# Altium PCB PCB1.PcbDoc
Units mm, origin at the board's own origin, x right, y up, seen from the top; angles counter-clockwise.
Board outline 65 x 30 mm, 2 copper layers (Top Layer, Bottom Layer), stack 1.201 mm thick; 44 components, 63 nets, 248 pads, 174 vias.
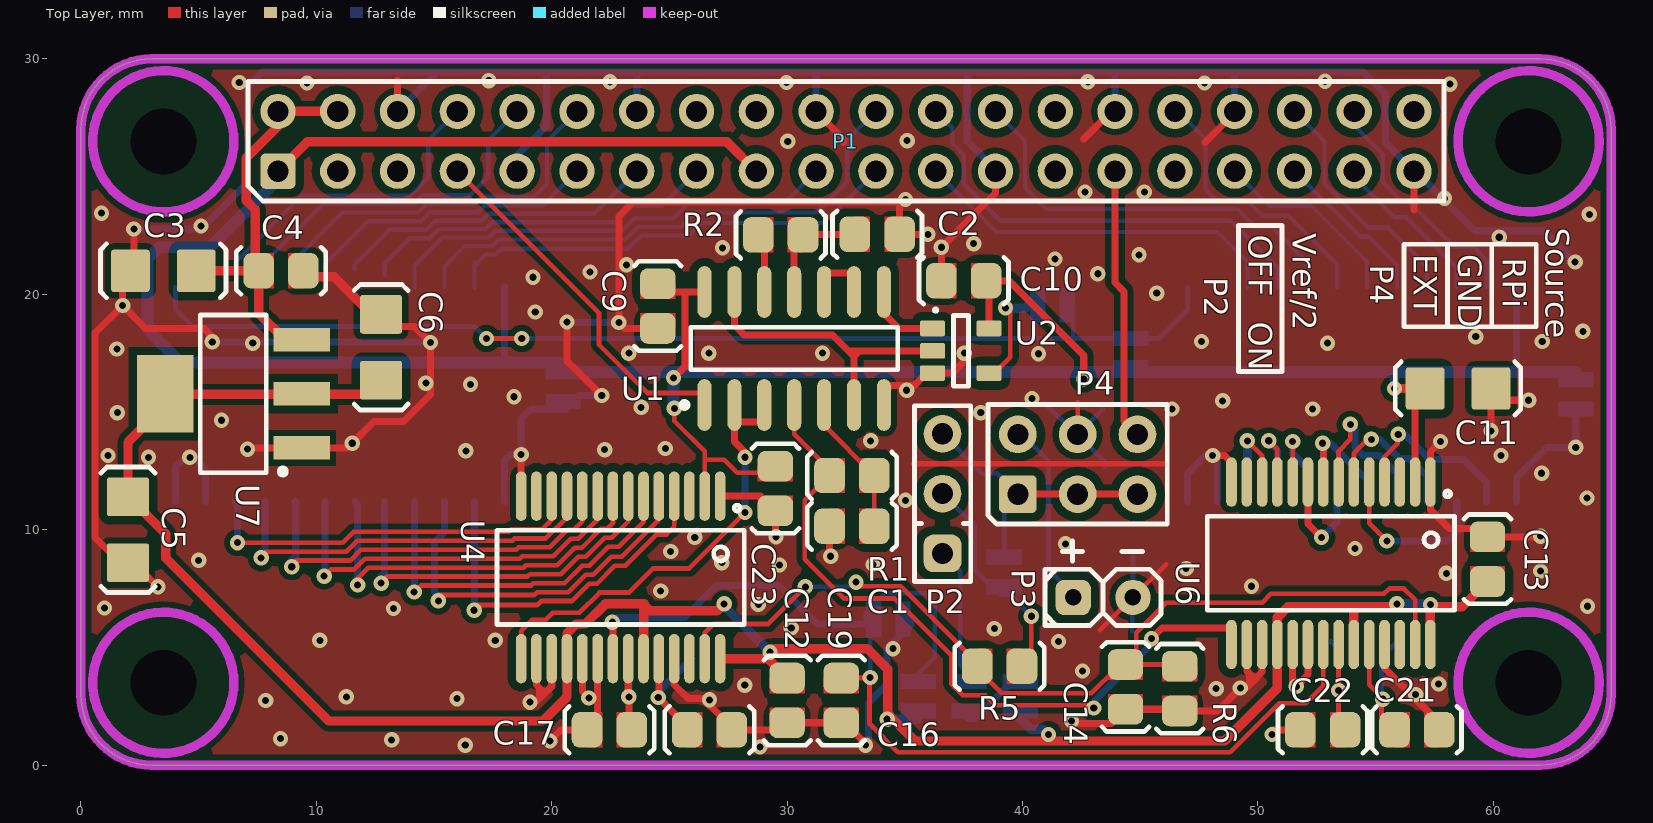
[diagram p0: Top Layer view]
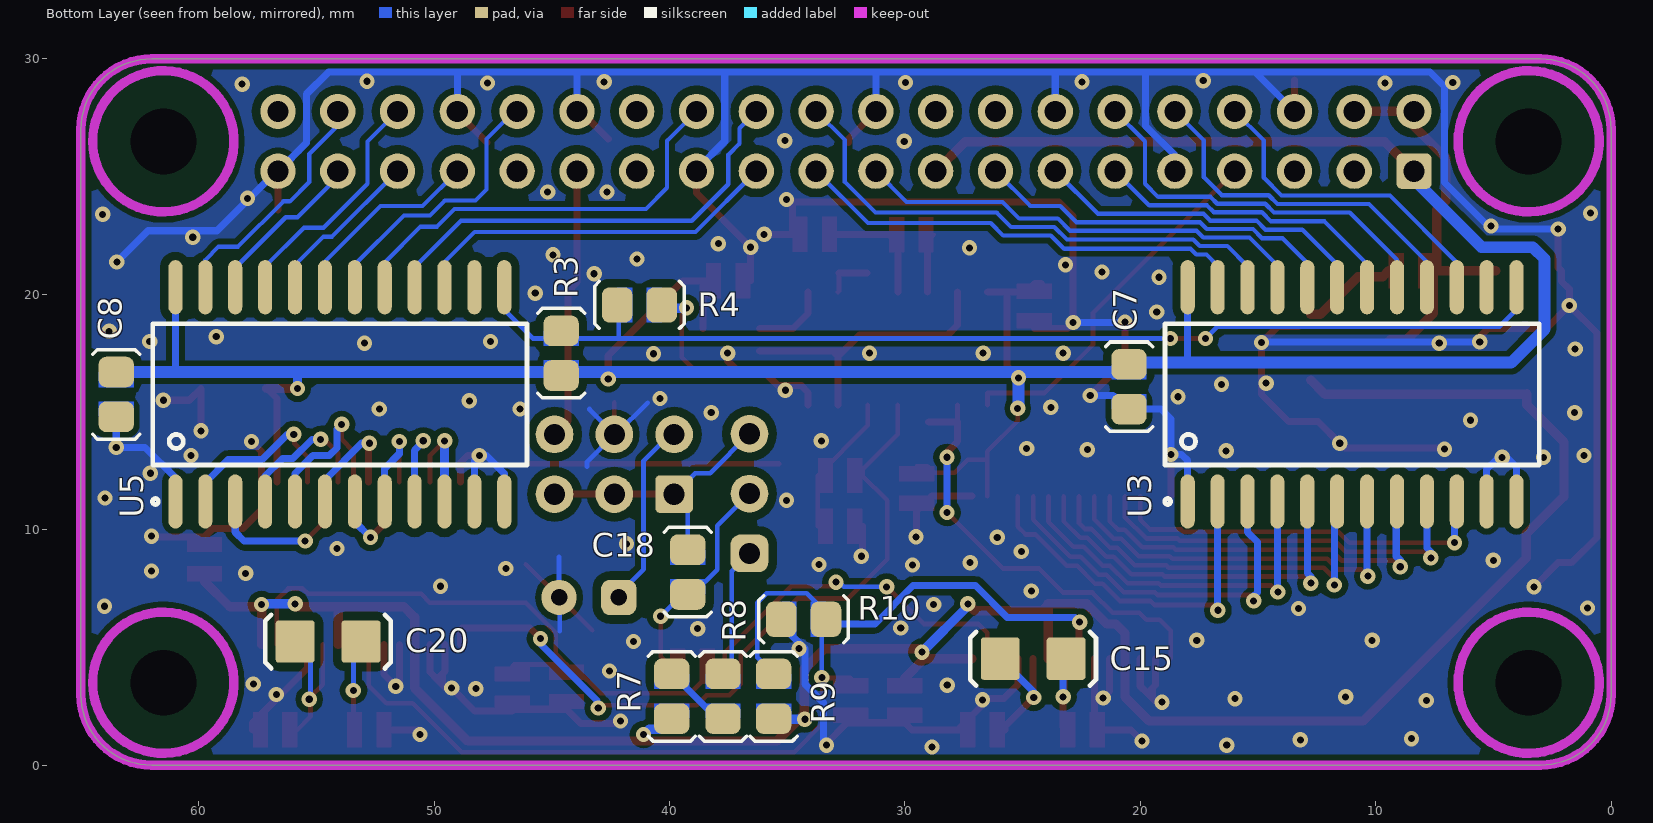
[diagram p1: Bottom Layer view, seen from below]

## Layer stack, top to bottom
Top Solder: solder mask 0.0102, Solder Resist, Dk 3.5
Top Layer: signal copper 0.0356
Dielectric 1: dielectric 1.13, FR-4, Dk 4.8
Bottom Layer: signal copper 0.0356
Bottom Solder: solder mask 0.0102, Solder Resist, Dk 3.5

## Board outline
0,3 0,27 cw(c3,27) 3,30 62,30 cw(c62,27) 65,27 65,3 cw(c62,3) 62,0 3,0 cw(c3,3)

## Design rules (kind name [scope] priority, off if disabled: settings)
Clearance Clearance_2 [Name Like '*-1111'] p1: gap=1 ignorepadtopadclearanceinfootprint=FALSE except(0: Arc-Hole Track-Hole SMDPad-Hole THPad-Hole Via-Hole Fill-Hole Poly-Hole Region-Hole Text-Hole)
Clearance Clearance_1 [InPolygon vs IsPad] p2: gap=0.356 ignorepadtopadclearanceinfootprint=FALSE except(0: Arc-Hole Track-Hole SMDPad-Hole THPad-Hole Via-Hole Fill-Hole Poly-Hole Region-Hole Text-Hole)
Clearance Clearance_3 [InPolygon] p3: gap=0.25 ignorepadtopadclearanceinfootprint=FALSE except(0: Arc-Hole Track-Hole SMDPad-Hole THPad-Hole Via-Hole Fill-Hole Poly-Hole Region-Hole Text-Hole)
Clearance [All] p4: gap=0.18 ignorepadtopadclearanceinfootprint=FALSE except(0: Arc-Hole Track-Hole SMDPad-Hole THPad-Hole Via-Hole Fill-Hole Poly-Hole Region-Hole Text-Hole)
HoleSize [All] p1 off: absolutevalues=TRUE maxlimit=2.54 minlimit=0.025 maxpercent=80.000 minpercent=20.000
PasteMaskExpansion [All] p1: expansion=0.05
PolygonConnect PolygonConnect_1 [All vs IsVia] p1: connectstyle=Direct reliefconductorwidth=0.254 reliefentries=4 polygonreliefangle="90 Angle" airgapwidth=0.254
PolygonConnect [All] p2: connectstyle=NoConnect reliefconductorwidth=0.254 reliefentries=4 polygonreliefangle="90 Angle" airgapwidth=0.254
RoomDefinition Sheet1 [InComponentClass('Sheet1')] p1 off: confinementstyle=ConfineIn formatcopy=TRUE lockcomponents=FALSE outline 411,117.625 393.601,117.625 393.601,70 411,70
RoutingVias [All] p1: holewidth=0.3 width=0.65 viastyle="Through Hole" minholewidth=0.3 minwidth=0.65 maxholewidth=0.3 maxwidth=0.65
SolderMaskExpansion [All] p1: expansion=0.102
Width [All] p1: maxlimit=3.048 minlimit=0.18 preferedwidth=0.18
28 further rules are at their usual default settings.

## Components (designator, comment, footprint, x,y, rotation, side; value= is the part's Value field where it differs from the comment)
C1 "100p" 0805RC 32.75,10.15 r0 top
C2 "N.S." 0805RC 33.825,22.55 r180 top
C3 "10u" 1206RC 3.5,21 r0 top
C4 "0.1u" 0805RC 8.5,21 r180 top
C5 "10u" 1206RC 2,10 r90 top
C6 "10u" 1206RC 12.75,17.75 r270 top
C7 "0.1u" 0805RC 20.475,16.075 r90 bottom
C8 "0.1u" 0805RC 63.5,15.75 r90 bottom
C9 "0.1u" 0805RC 24.5,19.5 r90 top
C10 "0.1u" 0805RC 37.5,20.575 r0 top
C11 "10u" 1206RC 58.5,16 r180 top
C12 "0.1u" 0805RC 30,2.75 r90 top
C13 "0.1u" 0805RC 59.75,8.75 r270 top
C14 "N.S." 0805RC 44.375,3.325 r90 top
C15 "10u" 1206RC 24.55,4.525 r0 bottom
C16 "0.1u" 0805RC 26.7,1.5 r0 top
C17 "0.1u" 0805RC 22.45,1.5 r0 top
C18 "10n" 0805RC 39.225,8.2 r270 bottom
C19 "0.1u" 0805RC 32.3,2.75 r90 top
C20 "10u" 1206RC 54.5,5.25 r0 bottom
C21 "0.1u" 0805RC 56.75,1.5 r0 top
C22 "0.1u" 0805RC 52.75,1.5 r0 top
C23 "0.1u" 0805RC 29.5,11.75 r90 top
P1 "Header 20X2" PLD-40 32.5,26.5 r0 top locked
P2 "PLS-3" PLS-3 36.6,8.995 r270 top
P3 "Header 2" SCSL-2 42.15,7.125 r180 top
P4 "Header 3X2" PBD-6 42.34,12.78 r180 top
R1 "100" 0805R 32.75,12.3 r0 top
R2 "51" 0805R 29.725,22.525 r0 top
R3 "N.S." 0805R 44.6,17.5 r270 bottom
R4 "0" 0805R 41.275,19.55 r0 bottom
R5 "1k" 0805R 39.025,4.2 r0 top
R6 "1k" 0805R 46.675,3.25 r90 top
R7 "1k" 0805R 39.9,2.925 r270 bottom
R8 "1k" 0805R 37.725,2.925 r90 bottom
R9 "150" 0805R 35.575,2.925 r270 bottom
R10 "150" 0805R 34.3,6.2 r180 bottom
U1 "74LVC14AD" M14A_N 30.3,17.7 r90 top
U2 "SN74LVC1G02DBV" SOT-23-5L 37.375,17.6 r0 top
U3 "SN74LVC841ADW" DW024_N 11,15.75 r90 bottom
U4 "AD9200AR" RS-28_N 22.925,7.975 r270 top
U5 "SN74LVC841ADW" DW024_N 54,15.75 r90 bottom
U6 "AD9200AR" RS-28_N 53.1,8.575 r270 top
U7 "LD1117S33TR" SOT223-4N 6.475,15.775 r180 top

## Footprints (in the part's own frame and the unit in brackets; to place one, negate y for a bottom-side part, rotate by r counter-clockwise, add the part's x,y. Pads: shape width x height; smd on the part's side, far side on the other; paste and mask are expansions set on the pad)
0805R [mm] "Chip Resistor"
  rrect50% 1.3x1.5 smd paste-5 mask+0.102: 1(-0.95,0) 2(0.95,0)
  Top Layer region: 0.3,-0.75 0.95,-0.75 0.95,0.75 0.3,0.75
  Top Layer region: -0.95,-0.75 -0.3,-0.75 -0.3,0.75 -0.95,0.75
  silkscreen extent -1.9,-1 1.9,1, body extent -1.15,-0.67 1.15,0.68, height 0.76
0805RC [mm] "Chip Capacitor"
  rrect50% 1.3x1.5 smd paste-5 mask+0.102: 1(-0.95,0) 2(0.95,0)
  Top Layer region: -0.95,-0.75 -0.3,-0.75 -0.3,0.75 -0.95,0.75
  Top Layer region: 0.3,-0.75 0.95,-0.75 0.95,0.75 0.3,0.75
  silkscreen extent -1.9,-1 1.9,1, body extent -0.95,-0.56 1.05,0.64, height 1.2
1206RC [mm] "Chip Capacitor"
  rrect15% 1.65x1.8 smd paste-5: 1(-1.4,0) 2(1.4,0)
  silkscreen extent -2.67,-1.14 2.67,1.14, body extent -1.6,-0.81 1.6,0.79, height 1.6
DW024_N [mm] "SOIC, 24-Leads, Body 15.4x7.5mm, Pitch 1.27mm, IPC Medium Density"
  oval 2.3x0.6 smd: 1(-4.55,6.985) 2(-4.55,5.715) 3(-4.55,4.445) 4(-4.55,3.175) 5(-4.55,1.905) 6(-4.55,0.635) 7(-4.55,-0.635) 8(-4.55,-1.905) 9(-4.55,-3.175) 10(-4.55,-4.445) 11(-4.55,-5.715) 12(-4.55,-6.985) 13(4.55,-6.985) 14(4.55,-5.715) 15(4.55,-4.445) 16(4.55,-3.175) 17(4.55,-1.905) 18(4.55,-0.635) 19(4.55,0.635) 20(4.55,1.905) 21(4.55,3.175) 22(4.55,4.445) 23(4.55,5.715) 24(4.55,6.985)
  silkscreen extent -4.67,-7.95 3,7.96, body extent -5.25,-7.82 5.15,7.58, height 2.6
M14A_N [mm] "SOIC, 14-Leads, Body 8.6x3.9mm, Pitch 1.27mm, IPC Medium Density"
  oval 2.2x0.6 smd paste-5: 1(-2.4,3.81) 2(-2.4,2.54) 3(-2.4,1.27) 4(-2.4,0) 5(-2.4,-1.27) 6(-2.4,-2.54) 7(-2.4,-3.81) 8(2.4,-3.81) 9(2.4,-2.54) 10(2.4,-1.27) 11(2.4,0) 12(2.4,1.27) 13(2.4,2.54) 14(2.4,3.81)
  silkscreen extent -2.52,-4.4 0.9,4.78, body extent -3,-4.37 3,4.38, height 1.75
PBD-6 [mm] "Connector; Header; 5x2 Position"
  rrect25% 1.6x1.6 hole 0.9: 1(2.54,1.27)
  round 1.6 hole 0.9: 2(2.54,-1.27) 3(0,1.27) 4(0,-1.27) 5(-2.54,1.27) 6(-2.54,-1.27)
  silkscreen extent -3.81,-2.54 3.81,2.54, body extent -3.81,-2.5 3.81,2.5, height 8.45
PLD-40 [mm] "Connector 20x2"
  rrect30% 1.5x1.5 hole 0.9: 1(-24.13,-1.27)
  round 1.5 hole 0.9: 2(-24.13,1.27) 3(-21.59,-1.27) 4(-21.59,1.27) 5(-19.05,-1.27) 6(-19.05,1.27) 7(-16.51,-1.27) 8(-16.51,1.27) 9(-13.97,-1.27) 10(-13.97,1.27) 11(-11.43,-1.27) 12(-11.43,1.27) 13(-8.89,-1.27) 14(-8.89,1.27) 15(-6.35,-1.27) 16(-6.35,1.27) 17(-3.81,-1.27) 18(-3.81,1.27) 19(-1.27,-1.27) 20(-1.27,1.27) 21(1.27,-1.27) 22(1.27,1.27) 23(3.81,-1.27) 24(3.81,1.27) 25(6.35,-1.27) 26(6.35,1.27) 27(8.89,-1.27) 28(8.89,1.27) 29(11.43,-1.27) 30(11.43,1.27) 31(13.97,-1.27) 32(13.97,1.27) 33(16.51,-1.27) 34(16.51,1.27) 35(19.05,-1.27) 36(19.05,1.27) 37(21.59,-1.27) 38(21.59,1.27) 39(24.13,-1.27) 40(24.13,1.27)
  silkscreen extent -25.4,-2.54 25.4,2.54, body extent -25.4,-2.54 25.4,2.54, height 8.54
PLS-3 [mm]
  rrect50% 1.6x1.6 hole 0.9: 1(0,0)
  round 1.6 hole 0.9: 2(-2.54,0) 3(-5.08,0)
  silkscreen extent -6.27,-1.19 1.19,1.19, body extent -6.35,-1.27 1.27,1.27, height 8.64
RS-28_N [mm] "SOP, 28-Leads, Body 10.2x5.3mm, Pitch 0.65mm, IPC Medium Density"
  oval 2.1x0.45 smd: 1(-3.45,4.225) 2(-3.45,3.575) 3(-3.45,2.925) 4(-3.45,2.275) 5(-3.45,1.625) 6(-3.45,0.975) 7(-3.45,0.325) 8(-3.45,-0.325) 9(-3.45,-0.975) 10(-3.45,-1.625) 11(-3.45,-2.275) 12(-3.45,-2.925) 13(-3.45,-3.575) 14(-3.45,-4.225) 15(3.45,-4.225) 16(3.45,-3.575) 17(3.45,-2.925) 18(3.45,-2.275) 19(3.45,-1.625) 20(3.45,-0.975) 21(3.45,-0.325) 22(3.45,0.325) 23(3.45,0.975) 24(3.45,1.625) 25(3.45,2.275) 26(3.45,2.925) 27(3.45,3.575) 28(3.45,4.225)
  silkscreen extent -3.07,-5.25 2,5.25, body extent -3.88,-5.16 3.88,5.17, height 2.15
SCSL-2 [mm] "2 pin SCSL connector (DS1002)"
  rrect50% 1.5x1.5 hole 0.7: 1(0,0)
  round 1.5 hole 0.7: 2(-2.54,0)
  silkscreen extent -3.73,-1.19 1.19,1.19, body extent -3.81,-1.27 1.27,1.27, height 4.4
SOT223-4N [mm] "SOT223, 4-Leads, Body 6.5x3.5mm, Pitch 2.3mm, Lead Span 7mm, IPC Medium Density"
  rect 2.4x1 smd: 1(-2.9,2.3) 2(-2.9,0) 3(-2.9,-2.3)
  rect 2.4x3.3 smd: 4(2.9,0)
  silkscreen extent -2.23,-3.35 1.4,3.42, body extent -3.54,-3.25 3.54,3.25, height 1.65
SOT-23-5L [mm] "SOT23, 5-Leads, Body 2.9x1.6mm, Pitch 0.95mm, Lead Span 2.8mm, IPC Medium Density"
  rrect25% 1.067x0.671 smd paste-5: 1(-1.2,0.95) 2(-1.2,0) 3(-1.2,-0.95) 4(1.2,-0.95) 5(1.2,0.95)
  silkscreen extent -1.14,-1.5 0.33,1.8, body extent -1.33,-1.5 1.17,1.5, height 1.1

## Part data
C1 C2 C3 C4 C5 C6 C7 C8 C9 C10 C11 C12 C13 C14 C15 C16 C17 C18 C19 C20 C21 C22 C23: library part Cap, "Capacitor"
P1: "Header, 40-Pin"
P2: library part "Header 3", "3-pin general header"
P3: "2-pin general header"
P4: "Header, 3-Pin, Dual row"
R1 R2 R3 R4 R5 R6 R7 R8 R9 R10: library part Res1, "Resistor"
U1: library part 74ACT14SC, "Hex Schmitt-Trigger Inverter, 14-Pin SOIC, Commercial Grade"
U3 U5: "10-Bit Bus-Interface D-Type Latch with 3-State Outputs"
U4 U6: "Single 10-bit ADC Parallel 20MSPS", Manufacturer="Analog Devices", Part Number=AD9200
U7: "Fixed Low Drop Positive Voltage Regulator, 3.3V, 4-Pin SOT-223, Tape and Reel"

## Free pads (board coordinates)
  round 0 hole 2.8 unplated mask+1.8: 0(3.5,3.5) 0(3.5,26.5) 0(61.5,3.5) 0(61.5,26.5)

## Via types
v1: diameter 0.65, hole 0.3, Top Layer to Bottom Layer, tented both sides, 174 vias

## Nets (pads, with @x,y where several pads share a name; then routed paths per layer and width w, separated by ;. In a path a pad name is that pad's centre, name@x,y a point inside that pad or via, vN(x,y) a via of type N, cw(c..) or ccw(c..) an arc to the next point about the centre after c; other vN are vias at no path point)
+5V: C3.2 C4.2 P1.2 P1.4 U7.3 | length 16.6
  Top Layer w0.4: C3.2 C4.2 7.55,19.2 8.675,18.075 U7.3 ; C4.2@7.406,21.144 7.406,23.594 7.028,23.972 7.028,25.798 8.37,27.14 P1.2 P1.4
A_IN: P1.29 P4.6 | length 11.6
  Top Layer w0.3: P1.29 43.93,20.495 44.3,20.125 44.3,14.63 P4.6
ADC_CLK1: U1.2 U1.3 U4.15 | length 18.9
  Top Layer w0.2: U4.15 18.7,5.7 19.175,6.175 19.75,6.175 20.05,6.475 21.175,6.475 22.03,7.33 23.28,7.33 24.3,8.35 25.827,8.35 v1(28.206,10.729) ; U1.2 U1.2@27.76,14.585 ; v1@28.2,13.3 28.2,13 28.206,13.006 v1(28.206,13.079) ; U1.2@27.76,14.585 27.76,14.575 27.75,14.575 U1.2@27.76,14.585
  Top Layer w0.3: v1@28.2,13.3 27.76,13.74 27.76,14.575 U1.3@29,14.575
  Bottom Layer w0.3: v1(28.206,10.729) v1(28.206,13.079)
ADC_CLK2: R1.1 U1.4 U6.15 | length 31.3
  Top Layer w0.2: U1.4 30.3,14.05 31.8,12.55 R1.1 30.75,11.25 30.75,8.75 32.425,7.075 34.575,7.075 36.975,4.675 36.975,3.45 37.45,2.975 38.425,2.975 38.85,2.55 v1@42.875,2.55
  Top Layer w0.3: v1(45.475,5.375) 45.925,5.825 48.8,5.825 48.875,5.75 U6.15
  Bottom Layer w0.3: v1(43.025,2.425) 43.075,2.475 43.075,2.75 45.475,5.15 v1(45.475,5.375) v1@45.4,5.3
AVCC: C5.2 C6.2 C12.2 C13.2 R7.2 R9.2 U4.18 U4.23 U4.28 U6.18 U6.23 U6.28 U7.2 U7.4 | length 100.8
  Top Layer w0.4: C6.2 12.15,15.75 3.6,15.75 U7.4 3.575,15.3 2,13.725 C5.2 2.025,11.4 3.6,9.825 3.6,8.8 10.525,1.875 19.625,1.875 20.65,2.9 U4.18 20.65,5.6 21.045,5.995 21.424,5.995 22.279,6.85 23.925,6.85 ; U4.23 23.9,6.825 24.175,6.55 27.025,6.55 v1(27.325,6.85) ; U4.28 29.175,4.525 C12.2 ; v1(29.275,4.8) 29.425,4.95 33.4,4.95 34.265,4.085 v1@34.265,1.965 ; v1(34.25,1.95) v1@34.265,1.965 ; v1@34.35,2.05 v1@34.265,1.965 ; v1@34.375,2.075 35.425,1.025 48.575,1.025 50.825,3.275 U6.18 50.825,6.275 51.275,6.725 54.075,6.725 ; U6.23 54.075,6.725 ; v1(55.9,6.85) 55.9,6.725 54.075,6.725 ; U6.28 57.325,6.725 58.675,6.725 C13.2
  Bottom Layer w0.4: v1(27.325,6.85) 27.325,6.75 v1(29.275,4.8) v1@29.35,4.8 ; v1(34.25,1.95) R9.2@35.525,1.95 ; R7.2 40.35,1.525 40.85,1.525 41.075,1.3 v1(41.1,1.3) ; v1(55.9,6.85) 57.3,6.85 v1(57.325,6.825)
CLK_IN: P1.7 U1.1 | length 15.7
  Top Layer w0.2: P1.7 22.006,19.214 22.006,17.869 24.07,15.805 26.49,15.805 U1.1
DA0: P1.21 U3.23 | length 19.8
  Bottom Layer w0.18: U3.23 U3.23@16.715,21.215 ; U3.23@16.715,21.34 U3.23@16.715,21.215 ; P1.21 31.565,23.025 26.35,23.025 25.825,22.5 23.8,22.5 23.233,21.933 17.867,21.933 17.624,21.69 17.19,21.69 U3.23@16.715,21.215
DA1: P1.22 U3.22 | length 23
  Bottom Layer w0.18: U3.22 15.445,21.195 16.3,22.05 17.475,22.05 17.75,22.325 23.116,22.325 23.651,22.86 25.485,22.86 26.1,23.475 31.25,23.475 32.55,24.775 32.55,26.55 P1.22
DA2: P1.19 U3.21 | length 19.6
  Bottom Layer w0.18: U3.21 14.175,21.222 15.363,22.41 17.326,22.41 17.616,22.7 22.982,22.7 23.502,23.22 25.145,23.22 25.85,23.925 29.925,23.925 P1.19
DA3: P1.15 U3.20 | length 15.4
  Bottom Layer w0.18: U3.20@12.905,20.8 12.905,21.33 13.955,22.38 14.824,22.38 15.214,22.77 17.177,22.77 17.467,23.06 22.71,23.06 23.4,23.75 24.67,23.75 P1.15
DA4: P1.13 U3.19 | length 13.8
  Bottom Layer w0.18: U3.19@11.635,21.05 11.635,21.26 13.115,22.74 14.675,22.74 15.065,23.13 17.028,23.13 17.318,23.42 21.8,23.42 P1.13
DA5: P1.11 U3.18 | length 12.6
  Bottom Layer w0.18: U3.18@10.365,21.05 10.365,21.29 12.175,23.1 14.45,23.1 14.84,23.49 16.879,23.49 17.169,23.78 19.62,23.78 P1.11
DA6: P1.12 U3.17 | length 16.1
  Bottom Layer w0.18: U3.17@9.095,21.05 9.095,21.47 11.1,23.475 14.316,23.475 14.691,23.85 16.729,23.85 17.019,24.14 19.24,24.14 19.8,24.7 19.8,26.5 P1.12
DA7: P1.10 U3.16 | length 14.6
  Bottom Layer w0.18: U3.16@7.825,21.05 7.825,21.375 10.285,23.835 14.167,23.835 14.542,24.21 16.535,24.21 17.3,24.975 17.3,26.54 P1.10
DA8: P1.8 U3.15 | length 13.3
  Bottom Layer w0.18: U3.15@6.555,21.05 6.555,21.355 9.395,24.195 13.995,24.195 14.75,24.95 14.75,26.53 P1.8
DB0: P1.38 U5.23 | length 10.4
  Bottom Layer w0.18: P1.38 54.09,27.166 55.3,25.956 55.3,24.775 56.125,23.95 56.4,23.95 58.325,22.025 59.15,22.025 59.715,21.46 U5.23
DB1: P1.37 U5.22 | length 7
  Bottom Layer w0.18: P1.37 54.09,24.985 55.8,23.275 56.3,23.275 58.445,21.13 U5.22
DB2: P1.36 U5.21 | length 10.3
  Bottom Layer w0.18: P1.36 52.825,26.495 52.825,24.7 54.7,22.825 55.525,22.825 57.175,21.175 U5.21
DB3: P1.35 U5.20 | length 7
  Bottom Layer w0.18: P1.35 54.33,22.45 54.7,22.45 55.905,21.245 U5.20
DB4: P1.33 U5.19 | length 8.3
  Bottom Layer w0.18: P1.33 50.49,23.75 52.275,23.75 54.635,21.39 U5.19
DB5: P1.32 U5.18 | length 11.8
  Bottom Layer w0.18: P1.32 46.605,27.77 47.775,26.6 47.775,24.45 48.24,23.985 49.54,23.985 50.175,23.35 51.275,23.35 53.365,21.26 U5.18
DB6: P1.26 U5.17 | length 18.1
  Bottom Layer w0.18: P1.26 40.1,26.52 40.1,24.525 41,23.625 49.125,23.625 49.875,22.875 50.575,22.875 52.095,21.355 U5.17
DB7: P1.24 U5.16 | length 19.2
  Bottom Layer w0.18: P1.24 37.025,27.055 37.025,26.4 37.5,25.925 37.5,24.675 39.05,23.125 48.85,23.125 50.825,21.15 U5.16
DB8: P1.23 U5.15 | length 15.9
  Bottom Layer w0.18: P1.23 38.89,22.65 48.275,22.65 49.555,21.37 U5.15
GND: C1.1 C2.1 C3.1 C4.1 C5.1 C6.1 C7.1 C8.1 C9.1 C10.1 C11.1 C12.1 C13.1 C14.1 C16.2 C17.1 C19.1 C21.2 C22.1 C23.1 P1.6 P1.9 P1.14 P1.20 P1.25 P1.30 P1.34 P1.39 P3.2 P4.4 R6.1 R10.1 U1.7 U2.3 U3.1 U3.11 U3.12 U4.1 U4.14 U4.16 U4.17 U4.19 U4.20 U4.25 U5.1 U5.11 U5.12 U6.1 U6.14 U6.16 U6.17 U6.19 U6.20 U6.25 U7.1 | length 300.1
  Top Layer w0.2: P4.4 42.34,15.415 ; 43.275,5.725 P3.2@44.675,7.125 ; P3.2@44.65,7.3 P3.2@44.665,7.3 ; P3.2 46.1,8.535
  Top Layer w0.22: 35.35,12.8 46,12.8
  Top Layer w0.3: v1(2.25,22.775) 2.25,21.15 C3.1 2.1,20.55 1.775,20.225 v1(1.775,19.525) ; v1(3.275,7.575) 2.25,8.6 C5.1 1.675,8.6 0.6,9.675 0.6,18.35 v1(1.775,19.525) ; v1(5.58,17.979) 5.559,18 5.559,18.216 5.225,18.55 2.75,18.55 v1(1.775,19.525) ; v1@7.125,13.475 U7.1 11.325,13.475 v1(11.525,13.675) 12.45,14.6 13.7,14.6 14.85,15.75 v1(14.85,17.95) 14.175,18.625 C6.1@13.275,18.625 ; P1.6 13.45,29.1 ; U4.14 v1(18.7,13.2) ; v1(19.075,2.675) 19.325,2.675 19.475,2.825 ; U4.16 19.35,3.4 19.475,3.275 ; v1(19.925,1.025) 20.4,1.5 C17.1 ; U4.17 20,3.35 19.7,3.05 ; v1(20.65,18.825) 20.65,17.175 v1(22.125,15.7) ; U4.19 21.3,3.125 v1(21.575,2.85) 21.95,2.85 ; C17.1@21.95,1.95 21.95,2.85 ; U4.20 21.95,2.85 ; C9.1 23.1,18.55 v1(22.85,18.8) 22.85,23.325 23.45,23.925 34.775,23.925 C2.1 v1(35.975,22.55) ; U4.25 25.2,3.425 25.8,2.825 26.425,2.825 C16.2@27.65,1.6 ; U4.1 28.875,11.425 C23.1 29.5,9.725 v1(29.525,9.7) ; C16.2 29.7,1.5 C12.1 C19.1 32.45,1.8 33.325,0.925 v1(33.325,0.85) ; P1.20 32.4,26.6 32.4,26.45 ; C1.1 31.8,8.925 v1(31.85,8.875) ; U1.7 34.11,15.835 34.4,16.125 35.4,16.125 35.925,16.65 U2.3 37,16.65 37.525,17.175 v1(37.525,17.5) ; C10.1 v1(36.55,22) 38.85,24.3 P1.25 ; v1(42.075,1.875) 42.18,1.77 43.77,1.77 C14.1 46.6,2.375 R6.1 48.275,2.3 v1(49.25,3.275) 49.5,3.275 49.65,3.425 ; 42.6,26.6 43.77,27.77 P1.30 ; 47.75,26.45 49.01,27.71 P1.34 ; v1(48.075,13.15) 48.575,13.15 48.875,12.85 U6.14 ; U6.16 49.525,4 49.65,3.875 ; U6.17 50.175,3.95 49.875,3.65 ; v1(50.6,1.3) 50.6,1.5 C22.1 ; U6.19 51.475,3.5 v1(51.625,3.35) 52.125,3.85 U6.20 ; U6.25 55.375,4.125 57.7,1.8 C21.2 ; 56.63,23.58 P1.39 ; v1(57.75,13.75) 57.325,13.325 U6.1 57.325,10.85 58.125,10.05 59.4,10.05 C13.1 61.975,9.7 v1(62,9.725) ; v1@59.9,14.45 C11.1 60.4,15.5 v1(61.5,15.5) ; 19.475,2.825 19.7,3.05 ; 19.475,2.825 19.475,3.275 ; 19.475,3.275 19.7,3.05 ; 49.65,3.425 49.65,3.875 ; 49.65,3.425 49.875,3.65 ; 49.65,3.875 49.875,3.65
  Top Layer w0.4: C4.1 9.7,20.75 10.75,20.75 12.35,19.15 C6.1
  Bottom Layer w0.2: 40.925,15.4 42.275,14.05 P4.4 ; 43.4,15.125 43.4,15.11 P4.4 ; 43.5,12.675 43.5,12.89 P4.4 ; 44.665,5.685 P3.2@44.665,7.3 ; P3.2 44.69,8.84
  Bottom Layer w0.3: v1(2.25,22.775) 5.1,22.775 7.075,24.75 7.075,28.825 7.7,29.45 15.13,29.45 ; U3.12 4.015,12.665 4.375,13.025 4.825,13.025 5.285,12.565 U3.11 ; v1(5.58,17.979) 14.821,17.979 v1(14.85,17.95) ; P1.6 15.13,29.45 ; U3.1 17.985,12.935 18.25,13.2 v1(18.7,13.2) 18.7,14.7 19.125,15.125 C7.1 20.575,15.125 21.15,15.7 v1(22.125,15.7) v1@22,15.575 ; P1.9 18.53,25.905 19.775,27.15 19.775,29.375 ; v1(20.65,18.825) 20.675,18.8 v1(22.85,18.8) ; P1.14 23.61,29.44 23.6,29.45 ; P1.20 31.23,29.445 31.225,29.45 ; v1@33.45,0.925 33.45,2.65 34.25,3.45 34.25,4.95 35.25,5.95 R10.1 ; P1.25 38.85,25.3 37.65,26.5 37.65,29.45 ; P1.30 43.93,29.38 ; U5.12 47.015,12.39 47.775,13.15 v1(48.075,13.15) 48.285,12.94 U5.11 ; P1.34 49.01,29.41 ; U5.1 60.985,12.21 62.275,13.5 v1(63.5,13.5) C8.1 ; v1(63.475,21.375) 62.15,22.7 59.225,22.7 56.695,25.23 P1.39 56.62,25.23 55.425,26.425 55.425,28.5 54.475,29.45 37.65,29.45 ; 15.13,29.45 23.6,29.45 ; 23.6,29.45 31.225,29.45 ; 31.225,29.45 37.65,29.45
  other v1: 28.85,0.775 16.325,0.85 13.2,1.075 8.475,1.125 7.85,2.75 26.7,2.775 15.975,2.825 11.275,2.9 56.7,3 48.225,3.25 28.2,3.4 57.675,3.45 42.55,4 34.5,4.95 41.525,5.25 10.15,5.3 17.6,5.3 38.8,5.8 30.175,5.825 13.275,6.65 1,6.675 64,6.75 28.775,6.825 24.625,7.4 49.725,7.6 58,8.15 62,8.25 46.95,8.35 29.675,8.5 33.65,8.525 27.225,8.6 5,8.7 25.05,9.075 54.125,9.2 41.825,9.4 26.075,9.675 35.025,11.25 63.975,11.35 62.05,12.4 2.875,13.075 4.625,13.075 1.15,13.15 60.325,13.15 16.35,13.35 22.25,13.4 7.075,13.425 24.825,13.45 33.55,13.775 59.9,14.2 5.975,14.65 1.55,14.975 38.225,14.975 46.35,15.125 52.325,15.125 23.8,15.2 48.5,15.475 40.4,15.575 18.4,15.65 35.075,15.925 16.55,16.175 14.65,16.225 40.675,17.475 23.275,17.5 26.675,17.5 31.5,17.5 1.525,17.675 7.3,17.925 52.95,17.925 47.6,18 62.075,18 59.25,18.2 63.8,18.425 19.3,19.25 45.7,20.05 19.2,20.725 43.2,20.875 21.625,20.95 23.175,21.25 41.375,21.5 44.95,21.675 27.25,21.975 37.925,22.15 60.25,22.425 5.1,22.9 64.075,23.4 0.875,23.45 35.025,24.025 57.925,24.075 42.65,24.35 45.175,24.35 30.025,26.5 35.1,26.525 58.15,28.925 9.6,28.975 47.725,28.975 6.725,29 29.975,29 22.475,29.025 42.775,29.025 52.85,29.05 17.325,29.075
LATCH: R3.1 R4.2 U3.13 U5.13 | length 47.4
  Top Layer w0.2: v1(17.225,18.125) v1(18.725,18.125)
  Bottom Layer w0.2: U3.13 4.015,19.36 4.737,18.638 16.712,18.638 v1(17.225,18.125) ; v1(18.725,18.125) 42.175,18.125 ; R4.2@42.15,19.55 42.15,18.15 42.175,18.125 ; U5.13 47.015,19.34 45.8,18.125 42.175,18.125
NetC1_2: C1.2 R1.2 U1.5 | length 6
  Top Layer w0.2: U1.5 31.57,14.43 R1.2 C1.2
NetC2_2: C2.2 R2.2 U1.11 | length 4.8
  Top Layer w0.2: R2.2@30.3,22.15 R2.2
  Top Layer w0.3: U1.11 R2.2@30.3,22.15 ; R2.2 30.7,22.55 C2.2
NetC14_2: C14.2 R5.1 R6.2 U4.27 U6.27 | length 41.1
  Top Layer w0.2: U4.27 26.5,5.625 26.875,6 29.2,6 v1(30.775,7.575) ; v1@32.875,7.775 v1(32.925,7.775) 33.1,7.6 34.825,7.6 37.65,4.775 37.65,4.525 39.125,3.05 42.925,3.05 44,4.125 44.225,4.125 C14.2 ; R6.2 46.6,4.275 C14.2 ; U6.27 56.675,7.025 56.2,7.5 55.575,7.5 55.35,7.275 50.55,7.275 50.175,6.9 46.095,6.9 44.825,5.63 44.825,4.725 C14.2
  Bottom Layer w0.2: v1(30.775,7.575) 32.6,7.575 32.8,7.775 v1(32.925,7.775)
NetC15_1: C15.1 C17.2 U4.22 | length 4.6
  Top Layer w0.3: U4.22 23.25,2.925 v1(23.275,2.9) C17.2@23.275,1.625
  Bottom Layer w0.3: C15.1 23.275,4.4 v1(23.275,2.9)
NetC15_2: C15.2 C16.1 U4.24 | length 5.8
  Top Layer w0.3: U4.24 24.55,2.9 v1(24.525,2.875) 25.75,1.65 C16.1
  Bottom Layer w0.3: v1(24.525,2.875) 24.525,3.1 C15.2
NetC18_1: C18.1 P2.3 P4.1 P4.3 P4.5 | length 11.9
  Top Layer w0.3: P4.1 P4.3 P4.5
  Bottom Layer w0.2: P2.3 38.275,12.4 38.91,12.4 P4.1 39.225,10.935 C18.1
NetC18_2: C18.2 P2.2 R5.2 | length 9.3
  Top Layer w0.2: R5.2 40.375,4.6 v1(40.375,6.325)
  Bottom Layer w0.2: P2.2 37.975,10.16 37.975,8.3 39.025,7.25 C18.2 39.45,7.25 v1(40.375,6.325)
NetC20_1: C20.1 C22.2 U6.22 | length 5.6
  Top Layer w0.2: C22.2@53.425,1.775 v1(53.425,3.175) U6.22
  Bottom Layer w0.2: C20.1 53.425,4.925 v1(53.425,3.175)
NetC20_2: C20.2 C21.1 U6.24 | length 6.8
  Top Layer w0.2: U6.24 54.725,3.425 55.25,2.9 55.25,2.05 C21.1
  Bottom Layer w0.2: v1(55.3,2.8) 55.25,2.85 55.25,4.6 C20.2
NetP2_1: P2.1 R8.2 | length 5.6
  Bottom Layer w0.2: P2.1 37.35,8.245 37.35,4.25 R8.2
NetP3_1: P3.1 P4.2 | length 7.8
  Bottom Layer w0.2: P4.2 39.975,14.05 41.1,12.925 41.1,8.325 P3.1@42.125,7.3
NetR2_1: R2.1 U1.12 | length 2.5
  Top Layer w0.2: R2.1 R2.1@29.03,22.27
  Top Layer w0.3: U1.12 R2.1@29.03,22.27
NetR4_1: R4.1 U2.4 | length 4.4
  Top Layer w0.2: U2.4 38.8,16.65 39.475,17.325 39.475,19.224 v1(39.274,19.425)
  Bottom Layer w0.4: v1(39.274,19.425) 39.299,19.4 40.1,19.4 R4.1@40.25,19.55
NetR7_1: R7.1 R8.1 | length 2.9
  Bottom Layer w0.3: R8.1@37.675,1.975 R8.1 R8.1@37.925,1.975 ; R8.1@37.975,1.975 R7.1@39.875,3.875
NetU1_6: U1.6 U1.13 U2.2 | length 13
  Top Layer w0.3: U1.13 27.76,18.69 28.175,18.275 31.925,18.275 32.6,17.6 ; U1.6 32.84,17.36 ; U2.2 33.08,17.6 ; 32.6,17.6 32.84,17.36 ; 32.6,17.6 33.08,17.6 ; 32.84,17.36 33.08,17.6
NetU1_8: U1.8 U2.1 | length 3.2
  Top Layer w0.3: U1.8 34.11,19.19 34.75,18.55 U2.1
NetU1_9: U1.9 U1.10 | length 2
  Top Layer w0.2: U1.9@32.8,20.9 32.8,20.14 U1.9
  Top Layer w0.3: U1.10@31.6,20.9 U1.9@32.8,20.9
NetU3_2: U3.2 U4.4 | length 16
  Top Layer w0.2: v1@16.65,6.634 16.816,6.8 19.38,6.8 19.55,6.97 20.857,6.97 21.597,7.71 21.922,7.71 22.682,8.47 23.132,8.47 24.462,9.8 24.875,9.8 25.2,10.125 U4.4
  Top Layer w0.3: v1@16.65,6.634 v1(16.706,6.579)
  Bottom Layer w0.3: v1(16.706,6.579) 16.715,6.588 U3.2
NetU3_3: U3.3 U4.5 | length 16.4
  Top Layer w0.2: v1(15.181,6.979) 15.2,6.998 15.2,7.225 19.25,7.225 19.375,7.35 20.7,7.35 21.44,8.09 21.765,8.09 22.525,8.85 22.975,8.85 24.55,10.425 U4.5
  Bottom Layer w0.3: v1(15.181,6.979) 15.181,7.181 15.025,7.336 15.025,9.475 15.445,9.895 U3.3
NetU3_4: U3.4 U4.6 | length 15.9
  Top Layer w0.2: v1(14.156,7.354) 14.432,7.63 19.118,7.63 19.218,7.73 20.543,7.73 21.288,8.475 21.6,8.475 22.4,9.275 22.837,9.275 23.9,10.338 U4.6
  Bottom Layer w0.3: v1(14.156,7.354) 14.175,7.373 U3.4
NetU3_5: U3.5 U4.7 | length 16.2
  Top Layer w0.2: v1(12.756,7.729) 12.756,7.781 12.985,8.01 18.96,8.01 19.06,8.11 20.385,8.11 21.13,8.855 21.443,8.855 22.243,9.655 22.555,9.655 23.25,10.35 U4.7
  Bottom Layer w0.2: v1@12.756,7.706 v1(12.756,7.729)
  Bottom Layer w0.3: v1(12.756,7.729) 12.756,8.006 12.905,8.155 U3.5
NetU3_6: U3.6 U4.8 | length 16.8
  Top Layer w0.2: v1(11.755,7.654) 11.75,7.659 11.75,7.93 12.21,8.39 18.803,8.39 18.903,8.49 20.228,8.49 20.973,9.235 21.285,9.235 22.085,10.035 22.36,10.035 22.6,10.275 U4.8
  Bottom Layer w0.2: v1(11.755,7.654) v1@11.755,7.795
  Bottom Layer w0.3: U3.6 11.755,11.08 v1@11.755,7.795
NetU3_7: U3.7 U4.9 | length 16.8
  Top Layer w0.2: v1(10.33,8.029) 10.612,8.31 11.593,8.31 12.053,8.77 18.645,8.77 18.745,8.87 20.07,8.87 20.815,9.615 21.128,9.615 21.95,10.437 U4.9
  Bottom Layer w0.3: v1(10.33,8.029) 10.365,8.063 U3.7
NetU3_8: U3.8 U4.10 | length 17.1
  Top Layer w0.2: v1(8.955,8.429) 8.955,8.505 9.14,8.69 11.435,8.69 11.895,9.15 18.488,9.15 18.588,9.25 19.913,9.25 20.658,9.995 20.945,9.995 21.3,10.35 U4.10
  Bottom Layer w0.3: v1(8.955,8.429) 8.955,8.705 9.125,8.875 9.125,11.17 U3.8
NetU3_9: U3.9 U4.11 | length 17.1
  Top Layer w0.2: v1(7.655,8.804) 7.655,8.88 7.845,9.07 11.278,9.07 11.738,9.53 18.331,9.53 18.431,9.63 19.744,9.63 20.65,10.536 U4.11
  Bottom Layer w0.3: v1(7.655,8.804) 7.655,9.055 7.825,9.225 U3.9
NetU3_10: U3.10 U4.12 | length 16.5
  Top Layer w0.2: v1(6.65,9.45) 11.12,9.45 11.58,9.91 18.173,9.91 18.273,10.01 19.585,10.01 20,10.425 U4.12
  Bottom Layer w0.3: U3.10 6.65,11.105 v1(6.65,9.45)
NetU5_2: U5.2 U6.4 | length 7.7
  Top Layer w0.2: U6.4 55.375,13.1 55.925,13.65 55.925,14.021 v1(55.958,14.054)
  Bottom Layer w0.3: v1(55.958,14.054) 56.221,14.054 57.3,12.975 58.75,12.975 59.715,12.01 U5.2
NetU5_3: U5.3 U6.5 | length 7.2
  Top Layer w0.2: U6.5 54.725,10.275 v1(55.475,9.525)
  Bottom Layer w0.3: v1(55.475,9.525) 58.075,9.525 58.445,9.895 U5.3
NetU5_4: U5.4 U6.6 | length 6.3
  Top Layer w0.2: U6.6 54.075,13.25 54.665,13.84 v1(54.815,13.84)
  Bottom Layer w0.3: v1(54.815,13.84) 55.185,13.84 56,13.025 56.425,13.025 57.175,12.275 U5.4
NetU5_5: U5.5 U6.7 | length 7.2
  Top Layer w0.2: U6.7 53.425,13.337 53.925,13.837 v1(53.925,14.475)
  Bottom Layer w0.3: v1(53.925,14.475) 54.125,14.275 54.125,13.475 54.45,13.15 55.15,13.15 55.905,12.395 U5.5
NetU5_6: U5.6 U6.8 | length 5.1
  Top Layer w0.3: v1(52.75,13.675) 52.775,13.65 U6.8
  Bottom Layer w0.3: v1(52.75,13.675) 53.075,13.675 54.635,12.115 U5.6
NetU5_7: U5.7 U6.9 | length 4.4
  Top Layer w0.3: U6.9 52.125,10.25 v1(52.7,9.675)
  Bottom Layer w0.3: v1(52.7,9.675) 53.365,10.34 U5.7
NetU5_8: U5.8 U6.10 | length 4.5
  Top Layer w0.2: U6.10 v1(51.475,13.75)
  Bottom Layer w0.3: v1(51.475,13.75) 51.475,13.225 52.095,12.605 U5.8
NetU5_9: U5.9 U6.11 | length 4.7
  Top Layer w0.2: v1@50.425,13.811 v1(50.457,13.779) 50.825,13.411 U6.11
  Bottom Layer w0.3: v1(50.457,13.779) 50.45,13.772 50.45,13.75 50.825,13.375 U5.9
NetU5_10: U5.10 U6.12 | length 4.6
  Top Layer w0.2: v1(49.55,13.775) 50.175,13.15 U6.12
  Bottom Layer w0.4: v1(49.55,13.775) 49.555,13.77 U5.10
REF_T: C19.2 R9.1 R10.2 U4.21 U6.21 | length 49.6
  Top Layer w0.2: C19.2@32.85,3.15 C19.2 v1@33.5,3.7 ; v1(33.525,3.725) v1@33.5,3.7 ; U6.21 52.775,3.375 52.025,2.625 50.9,2.625 48.82,0.545 34.705,0.545 33.5,1.75 v1@33.5,3.7
  Top Layer w0.3: v1(22.575,6.075) 22.6,6.05 U4.21
  Bottom Layer w0.2: R10.2 33.35,6.475 34.175,7.3 35.875,7.3 36.275,6.9 36.275,4.575 R9.1 ; v1(33.525,3.725) R10.2@33.525,6.025
  Bottom Layer w0.3: v1(22.575,6.075) 22.775,6.275 25.65,6.275 27,7.625 29.65,7.625 31.275,6 R10.2@33.325,6
VCC: C7.2 C8.2 C9.2 C10.2 C11.2 C23.2 P1.1 P1.17 R3.2 U1.14 U2.5 U3.24 U4.2 U5.24 U6.2 | length 130.4
  Top Layer w0.2: v1(25.206,15.154) 25.206,14.619 26.5,13.325 26.5,12.975 ; U4.2 26.5,12.975 ; C23.2 29.025,12.7 28.75,12.425 27.875,12.425 27.325,12.975 26.5,12.975
  Top Layer w0.3: C9.2@24.2,20.45 C9.2 24.85,20.1 25.67,20.1 ; v1(25.175,16.45) 25.67,16.945 25.67,20.1 ; U1.14 25.67,20.1 ; U2.5 38.575,20.45 C10.2 39.425,20.575 42.6,17.4 v1(42.6,16.4) ; U6.2 56.675,15.575 C11.2
  Top Layer w0.4: P1.1 9.615,26.475 27.445,26.475 P1.17 ; v1(55.8,16) C11.2
  Bottom Layer w0.3: 17.985,17.05 17.985,17.1 U3.24 ; v1(42.6,16.4) 42.6,16.65 v1@42.65,16.7 ; U5.24 60.985,16.815 61.1,16.7
  Bottom Layer w0.4: v1(55.8,16) 55.8,16.7
  Bottom Layer w0.5: P1.1 8.37,24.87 5.5,22 3.325,22 2.825,21.5 2.825,18.525 4.25,17.1 17.985,17.1 C7.2@20.325,17.1 ; C7.2@20.125,17.075 20.5,16.7 42.65,16.7 55.8,16.7 61.1,16.7 C8.2 ; v1(25.175,16.45) 25.175,15.185 v1(25.206,15.154)
pads on no net: P1.3 P1.5 P1.16 P1.18 P1.27 P1.28 P1.31 P1.40 U3.14 U4.3 U4.13 U4.26 U5.14 U6.3 U6.13 U6.26

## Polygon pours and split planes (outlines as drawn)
GND on Bottom Layer "B1p" (solid, remove dead copper, pour order 2): 0,30 0,0 65,0 65,30
GND on Top Layer "B1p" (solid, remove dead copper, pour order 4): 0,0 0,30 65,30 65,0

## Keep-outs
Keep-Out Layer:
  circle w0.4: c3.5,26.5 r3
  circle w0.4: c3.5,3.5 r3
  circle w0.4: c61.5,3.5 r3
  circle w0.4: c61.5,26.5 r3
  lines w0.4: 0,3 ccw(c3,3) 3,0 62,0 ccw(c62,3) 65,3 65,27 ccw(c62,27) 62,30 3,30 ccw(c3,27) 0,27 0,3

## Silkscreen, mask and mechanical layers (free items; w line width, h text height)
Top Overlay:
  lines w0.2: 41.687,9.075 42.562,9.075 ; 42.125,8.675 42.125,9.525 ; 44.225,9.075 45.1,9.075 ; 49.175,22.9 49.175,16.725 51.025,16.725 51.025,22.9 ; 49.175,22.925 51.025,22.925 ; 56.2,22.1 56.2,18.625 61.825,18.625 61.825,22.125 56.2,22.125 ; 58.05,18.675 58.05,22.1 ; 59.925,18.625 59.925,22.125
  text "Source" at 62.225,22.825 h1 r270
  text "Vref/2" at 51.475,22.6 h1 r270
  text "OFF" at 49.6,22.525 h1 r270
  text "EXT" at 56.625,21.7 h1 r270
  text "GND" at 58.5,21.7 h1 r270
  text "RPi" at 60.4,21.55 h1 r270
  text "P4" at 54.775,21.25 h1 r270
  text "P2" at 47.725,20.725 h1 r270
  text "ON" at 49.6,18.825 h1 r270
Shape:
  the board outline again, w0.1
